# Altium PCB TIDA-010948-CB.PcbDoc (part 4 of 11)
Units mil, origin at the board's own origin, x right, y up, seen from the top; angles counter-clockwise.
Board outline 8100 x 8400 mil, 8 copper layers (L01 - TOP, L02 - GND, L03 - SIG, L04 - GND, L05 - PWR, L06 - SIG, L07 - GND, L08 - BOTTOM), stack 59.656 mil thick; 711 components, 572 nets, 2646 pads, 1325 vias.
Unrouted connection lines stored in the file: 988.
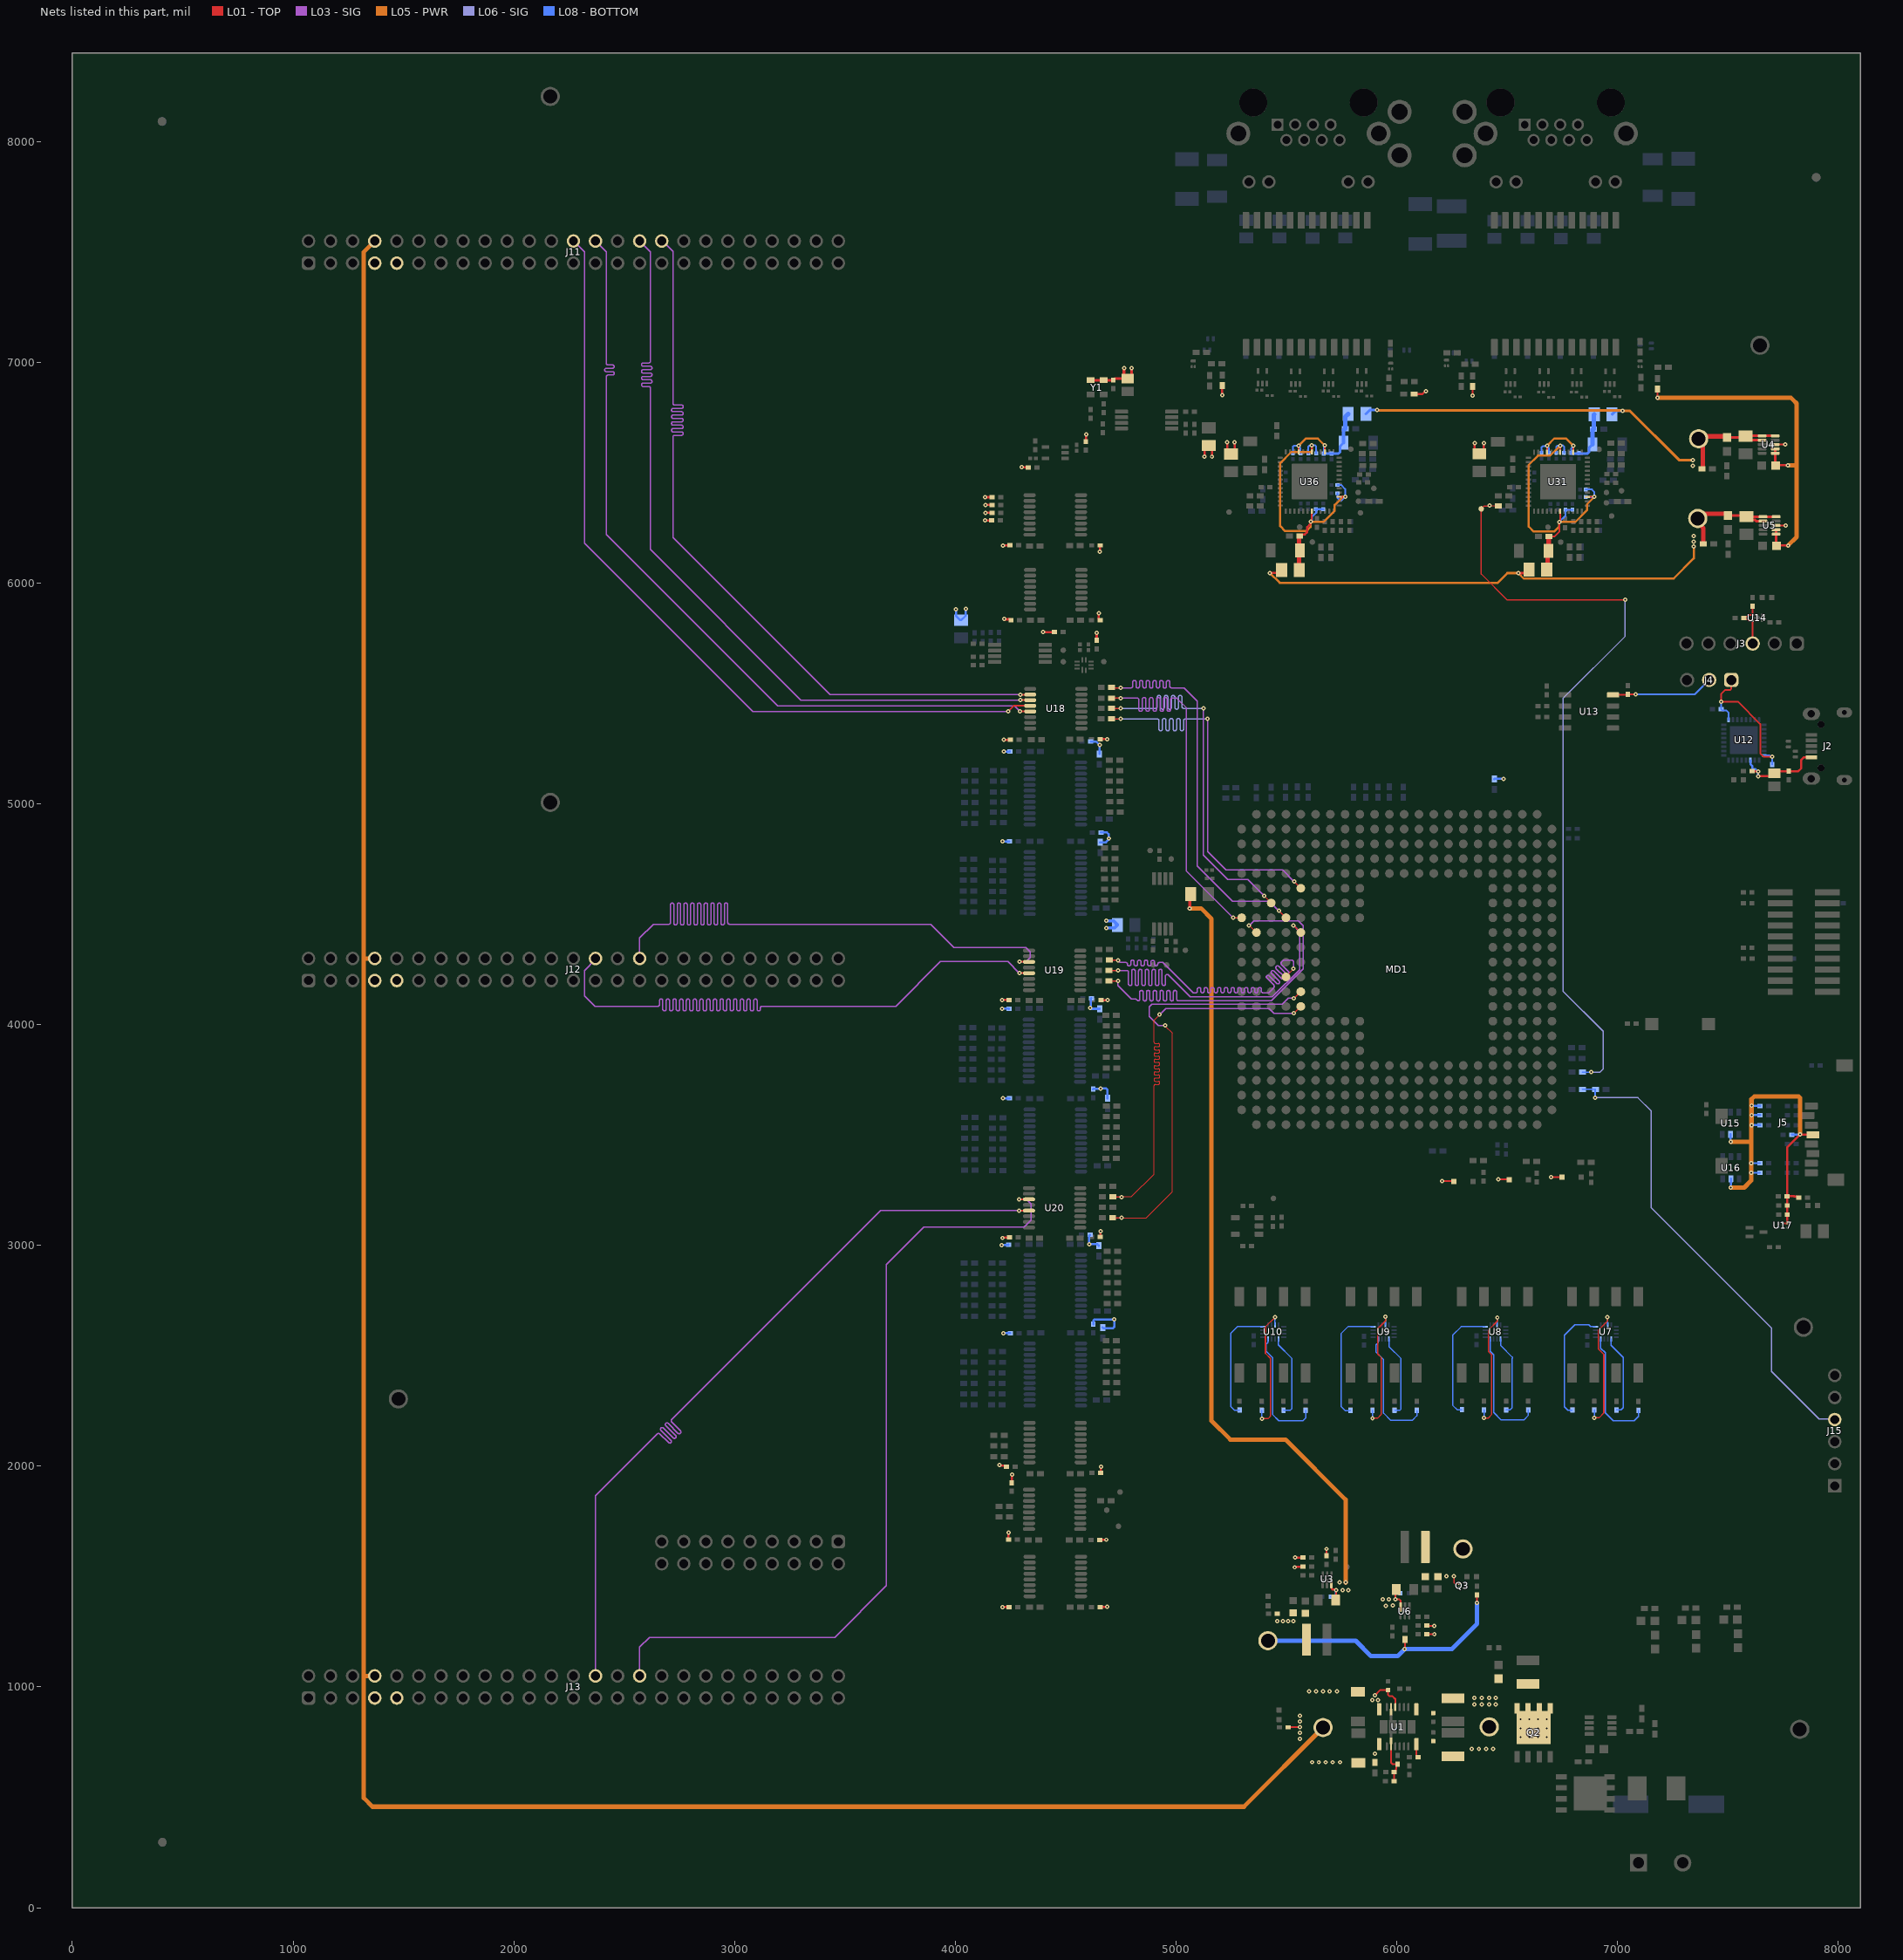
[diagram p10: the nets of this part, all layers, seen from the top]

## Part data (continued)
R229 R231 R245 R248 R269 R271 R285 R287: library part CMP-0021425-3, "RES, 75.0, 1%, 0.125 W, AEC-Q200 Grade 0, 0805", Manufacturer=Vishay-Dale, Power_W=125mW, Supplier Part Number 1=541-75.0CCT-ND, TempCo="100 ppm/C", Tolerance_%=1%, Value2=0.125W, Value_Code=75R0, ValueDisplayed=75.0
R235 R275: library part CMP-0025975-3, "RES, 11.0 k, 1%, 0.063 W, AEC-Q200 Grade 0, 0402", Manufacturer=Vishay-Dale, Power_W=63mW, Supplier Part Number 1=541-11.0KLCT-ND, TempCo="100 ppm/C", Tolerance_%=1%, Value2=0.063W, Value_Code=11k0, ValueDisplayed=11.0k
R236: library part CMP-0026890-5, "RES, 2.2 k, 5%, 0.063 W, AEC-Q200 Grade 0, 0402", Manufacturer=Vishay-Dale, Power_W=63mW, Supplier Part Number 1=541-2.2KJCT-ND, TempCo="200 ppm/C", Tolerance_%=5%, Value2=0.063W, Value_Code=2k20, ValueDisplayed=2.2k
R240 R244 R250 R251 R280 R284 R289 R290: library part CMP-0026852-1, "RES, 1.0 k, 5%, 0.063 W, 0402", Manufacturer=Vishay-Dale, Power_W=63mW, Supplier Part Number 1=541-1.0KJCT-ND, TempCo="200 ppm/C", Tolerance_%=5%, Value2=0.063W, Value_Code=1k00, ValueDisplayed=1.0k
R242 R243 R282 R283: library part CMP-0026231-2, "RES, 2.20 k, 1%, 0.063 W, AEC-Q200 Grade 0, 0402", Manufacturer=Vishay-Dale, Power_W=63mW, Supplier Part Number 1=541-2.20KLCT-ND, TempCo="100 ppm/C", Tolerance_%=1%, Value2=0.063W, Value_Code=2k20, ValueDisplayed=2.20k
R249 R252 R288: library part CMP-0016081-3, "RES, 1.0 M, 5%, 0.75 W, AEC-Q200 Grade 0, 2010", Manufacturer=Vishay-Dale, Power_W=750mW, Supplier Part Number 1=541-1.0MWCT-ND, TempCo="200 ppm/C", Tolerance_%=5%, Value2=0.75W, Value_Code=1M00, ValueDisplayed=1.0M
R311 R312 R313: library part CMP-0025332-3, "RES, 49.9 k, 0.5%, 0.1 W, 0603", Manufacturer="Yageo America", Power_W=100mW, TempCo="50 ppm/C", Tolerance_%=0.5%, Value2=0.1W, Value_Code=49k9, ValueDisplayed=49.9k
R314 R315 R316: library part CMP-0025223-3, "RES, 3.40 k, 0.5%, 0.1 W, 0603", Manufacturer="Yageo America", Power_W=100mW, TempCo="50 ppm/C", Tolerance_%=0.5%, Value2=0.1W, Value_Code=3k40, ValueDisplayed=3.40k
S1: library part CMP-0002196-2, "Switch, Tactile, SPST, 12 V, SMD", CurrentRating_mA=50A, Manufacturer="Wurth Elektronik", Supplier Part Number 1=31T8978
SW1 SW2 SW3 SW4: library part CMP-0096367-1, "Dip Switch SPST 4 Position Surface Mount Slide (Standard) Actuator 25mA 24VDC", Coil Resistance_ohm=50mΩ, Contact Current Rating=25mA, Digikey Part Number=732-6963-1-ND, Manufacturer="Wurth Electronics", Mouser Part Number=710-418121270804, Operating Temperature Range="-40°C to +85°C"
T1 T2: library part CMP-0086582-1, "WURTH ELEKTRONIK LAN TRANSFORMER, 10/100/1000 BASE-T", Manufacturer="Wurth Electronics"
TP1 TP2 TP3 TP4 TP5 TP6 TP7 TP8 TP9 TP34 TP40 TP41: library part CMP-0055160-1, "Test Point, Multipurpose, Purple, TH", Color=Purple, Manufacturer=Keystone, Supplier Part Number 1=36-5129-ND
TP10 TP11 TP12 TP13 TP14 TP15 TP16 TP17 TP18 TP19 TP20 TP21 TP22 TP23 TP24 TP25 TP26 TP27 TP28 TP29 TP30 TP31 TP32 TP33 TP35 TP36 TP37 TP38 TP39: library part CMP-0078143-3, "TEST POINT.  No entry in BOM.", Manufacturer=N/A
U1: library part CMP-0093355-3, "Cruzline-6A Power Module 36Vin 1 Ajustable-Output 1-6V B3QFN20 200-2200kHz SW Freq", Manufacturer="Texas Instruments", Max Supply Voltage=36V, Min Supply Voltage=3V, Operating Temperature Range="-40°C to +125°C", Output Voltage=1-6V, Switching Frequency=200-2200kHz
U2: library part CMP-0095578-1, "Low IQ High Side Switch Controller With Reverse Polarity and Overvoltage Protection", Manufacturer="Texas Instruments", Max Supply Voltage=60V, Min Supply Voltage=4V, Nominal Supply Current=45uA, Operating Temperature Range="-40°C to +150°C"
U3 U6: library part CMP-0083727-1, "4-A Step-Down Converter with 1% Output Accuracy, DMQ0006A (VSON-HR-6)", Alternate Manufacturer="Texas Instruments", Alternate PartNumber=TPS62827DMQR
U4 U5: library part CMP-0860376-1, "1A and 2-A High Efficiency Step-Down Converter MicroSiPTM with Integrated Inductor, SIL0010D (uSIP-10)", Alternate Manufacturer="Texas Instruments", Alternate PartNumber=TPSM82822SILT
U7 U8 U9 U10: library part CMP-0086167-2, "Low-capacitance, 2:1 (SPDT) 4-channel, powered-off protection switch with 1.8 V logic, RSV0016A (UQFN-16)", Alternate Manufacturer="Texas Instruments", Operating Temperature Range="-40 to 125 C", Rating=Catalog
U11: library part CMP-0051315-2, "Single Bus Buffer Gate with 3-State Output, DBV0005A (SOT-23-5)", F @ Nom Voltage(Max)(Mhz)=75, Generic Part Number=SN74AHC1G125, ICC @ Nom Voltage(Max)(mA)=0.01, Manufacturer="Texas Instruments", Operating Temperature Range="-40 to 125 C", Rating=Catalog, tpd @ Nom Voltage(Max)(ns)=11.5,7.5, Voltage(Nom)(V)=3.3,5
U12: library part CMP-0004929-1, "Future Technology Devices International Ltd. FT232R USB UART IC, QFN32", Manufacturer=FTDI, Supplier Part Number 1=768-1008-1-ND
U13: library part CMP-0085670-1, "High Speed, Robust EMC Reinforced Dual-Channel Digital Isolator, D0008B (SOIC-8)", Alternate Manufacturer="Texas Instruments", Alternate PartNumber=ISO7021DR, Operating Temperature Range="-55 to 125 C", PartNumber=ISO7021D, Rating=Catalog
U14: library part CMP-0035981-2, "Single Output Low Noise LDO, 200 mA, Fixed 3.3 V Output, 2 to 5.5 V Input, 4-pin X2SON(DQN), -40 to 85 degC, Green (RoHS & no Sb/Br)", Alternate Manufacturer="Texas Instruments", Alternate PartNumber=TLV70733DQNR
U15 U16: library part CMP-0043117-1, "ESD Solution for High-Speed Differential Interface, 4 Channels, -40 to +85 degC, 6-pin SOT-32 (DBV), Green (RoHS & no Sb/Br)", Breakdown Voltage(Min)(V)=9, Differential Capacitance(pF)=0.05, IO Capacitance(Typ)(pF)=0.8, IO Leakage Current(nA)=10, Manufacturer="Texas Instruments"
U17: library part CMP-0066658-1, "5.5V, 3A, 13.8mΩ Load Switch with Reverse Current Protection, YZP0006AFAF (DSBGA-6)", Alternate Manufacturer="Texas Instruments", Alternate PartNumber=TPS22963CYZPT
U18 U19 U20 U41 U42 U43 U44 U45: library part CMP-0079319-1, "Quad-Bit Bus Transceiver with Configurable Voltage Translation and 3-State Outputs, PW0016A (TSSOP-16)", Alternate Manufacturer="Texas Instruments", Alternate PartNumber=SN74AXC4T245PWR
U21: library part CMP-0860382-1, "SN74AXC2T245RSW, RSW0010A (UQFN-10)", Alternate Manufacturer="Texas Instruments"
U22: library part CMP-0091149-1, "Clock Clock Buffer IC 1:4 250MHz 8-TSSOP (0.173\", 4.40mm Width)", Digikey Part Number=296-LMK1C1102PWRCT-ND, Manufacturer="Texas Instruments", Max Supply Voltage=3.465V, Min Supply Voltage=1.71V, Mouser Part Number=595-LMK1C1102PWR, Nominal Supply Current=25-33000uA, Operating Temperature Range="-40°C to +125°C"
U23 U24: library part CMP-0096980-1, "1.8-V, 2.5-V, and 3.3-V LVCMOS Clock Buffer Family", Digikey Part Number=296-LMK1C1104PWRCT-ND, Manufacturer="Texas Instruments", Max Supply Voltage=3.465V, Min Supply Voltage=1.71V, Mouser Part Number=595-LMK1C1104PWR, Nominal Supply Current=25-33000uA, Operating Temperature Range="-40°C to +125°C"
U25 U26 U27 U28 U29 U30: library part CMP-0065205-4, "Asynchronous Communication Between Data Buses, PW0024A (TSSOP-24)", Alternate Manufacturer="Texas Instruments", Alternate PartNumber=SN74AXC8T245PWT, Operating Temperature Range="-40 to 125 C", Rating=Catalog
U31 U36: library part CMP-0091377-1, "1/1 Transceiver Ethernet 48-VQFN (7x7)", Digikey Part Number=296-53377-1-ND, Manufacturer="Texas Instruments", Max Supply Voltage=3.45V, Min Supply Voltage=990mV, Mouser Part Number=595-DP83869HMRGZT, Operating Temperature Range="-40°C to +125°C"
U32 U33 U34 U35 U37 U38 U39 U40: library part CMP-0066602-2, "Dual-Channel High-Speed ESD Protection, DRL0005A (SOT-OTHER-5)", Alternate Manufacturer="Texas Instruments"
U46: library part CMP-0078475-5, "1-Bit Dual-Supply Buffered Voltage Signal Converter, DCK0005A (SOT-SC70-5)", Manufacturer="Texas Instruments"
Y1: library part CMP-0096024-1, "High-Performance BAW Oscillator", Frequency Stability=25ppm, Frequency_Fixed=25MHz, Load Capacitance=30pF, Manufacturer="Texas Instruments", Max Supply Current=50mA, Max Supply Voltage=3.465V, Min Supply Voltage=2.375V, Operating Temperature Range="-40°C to +105°C"

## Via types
v1: diameter 19.68, hole 7.87, L01 - TOP to L08 - BOTTOM, 1310 vias
v2: diameter 20, hole 7.87, L01 - TOP to L08 - BOTTOM, tented both sides, 7 vias
v3: diameter 200, hole 144, L01 - TOP to L08 - BOTTOM, 6 vias
v4: diameter 20, hole 8, L01 - TOP to L08 - BOTTOM, tented both sides, 2 vias

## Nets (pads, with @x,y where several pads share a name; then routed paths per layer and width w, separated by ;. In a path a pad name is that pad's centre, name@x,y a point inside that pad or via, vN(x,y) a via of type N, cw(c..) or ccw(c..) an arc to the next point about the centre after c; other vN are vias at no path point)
1V1: C23.1 C24.1 L8.2 L11.2 R20.2 TP7.1 U5.5 U5.6 U5.7 | length 2745.9
  L01 - TOP w10: v1(5425.5,6045.5) 5464.5,6045.5 L11.2@5478,6059 ; v1(6550.36,6045.03) 6583.53,6045.03 L8.2@6599,6060.5
  L01 - TOP w12: C23.1@7499.61,6305.54 7580.11,6305.54 C24.1@7584.61,6301.05 C24.1@7585.24,6300.42 ; U5.7@7659.08,6280.73 7627.92,6280.73 7622.63,6286.03 7599.63,6286.03 C24.1@7585.24,6300.42 ; U5.5@7718.14,6300.42 U5.6@7659.08,6300.42 C24.1@7585.24,6300.42
  L01 - TOP w20: R20.2@7388.99,6178.05 7388.99,6248.88 7363.5,6274.37 TP7.1@7363.5,6292.5 7384.05,6313.05 7492.1,6313.05 C23.1@7499.61,6305.54
  L05 - PWR w10: v1(5425.5,6045.5) 5469.46,6001.54 6457.4,6001.54 6500.89,6045.03 v1(6550.36,6045.03) 6574.89,6020.5 7254,6020.5 7345.61,6112.11 v1(7345.61,6165.05)
  other v1: 7345.61,6188.05 7345.61,6212.05
1V1_ETH1: C116.1 C117.1 C118.1 C119.1 C123.1 C129.1 C130.1 C131.1 L8.1 U31.6 U31.31 U31.39 | length 1522.8
  L01 - TOP w8: C123.1@6689.62,6211.5 6715.21,6211.5 6735.86,6232.15 v1(6735.86,6277.03) 6735.86,6280.19 6739.84,6284.17 U31.31@6739.84,6325.14 ; U31.6@6739.85,6592.87 v1(6739.85,6622.52) ; U31.39@6863.86,6390.1 6863.97,6389.99 6895.1,6389.99 v1(6895.21,6389.88)
  L01 - TOP w20: L8.1@6679,6060.5 6682.71,6064.21 6682.71,6142.29 C116.1@6686.43,6146 6688.03,6147.6 6688.03,6209.9 C123.1@6689.62,6211.5
  L05 - PWR w10: v1(6739.85,6622.52) 6694.08,6576.75 6639.55,6576.75 6597.13,6534.33 6597.13,6255.87 6619.85,6233.15 6712.52,6233.15 6735.86,6256.49 v1(6735.86,6277.03) 6808.53,6277.03 6861.5,6330 6861.5,6356.17 v1(6895.21,6389.88)
  L08 - BOTTOM w8: C118.1@6722.5,6589.99 6722.5,6617.31 6727.19,6622 6739.33,6622 v1(6739.85,6622.52) 6740.33,6623 6752.81,6623 6757.5,6618.31 C130.1@6757.5,6589.99 ; v1(6735.86,6277.03) 6764,6305.17 C117.1@6764,6332.01 C129.1@6796,6332.01 ; C119.1@6855.99,6389.5 6856.26,6389.76 6895.09,6389.76 6895.36,6390.03 6895.36,6412.14 6884,6423.5 C131.1@6855.99,6423.5
1V1_ETH2: C158.1 C159.1 C160.1 C161.1 C165.1 C171.1 C172.1 C173.1 L11.1 U36.6 U36.31 U36.39 | length 1559.8
  L01 - TOP w8: v1@5614.98,6284.65 U36.31@5614.98,6325.61 ; U36.6@5614.98,6593.33 v1(5615,6623) ; U36.39@5739,6390.57 5739.21,6390.79 5765.79,6390.79 v1(5766,6391)
  L01 - TOP w10: C165.1@5560.12,6213.5 5566.93,6220.31 5583.31,6220.31 5594,6231 5594,6253 5604,6263 5605.14,6263 5609.15,6267 5609.15,6275.65 v1(5611,6277.5)
  L01 - TOP w20: L11.1@5558,6059 5558,6211.69 5559.81,6213.5 C165.1@5560.12,6213.5
  L05 - PWR w10: v1(5615,6623) 5614.99,6599.19 5609.13,6593.33 5521.51,6593.33 5471.51,6543.33 5471.51,6258.1 5494.45,6235.15 5590.65,6235.15 5609.5,6254 5609.5,6276 v1(5611,6277.5) 5668.94,6277.5 5718.79,6327.35 5718.79,6353.68 5756.11,6391 v1(5766,6391)
  L08 - BOTTOM w8: C173.1@5599.5,6586.99 5599.5,6617.31 5604.19,6622 5614,6622 v1(5615,6623) 5630.31,6623 5635,6618.31 C161.1@5635,6586.99 ; C160.1@5730.99,6407 5730.99,6386.06 5742.71,6374.34 5749.34,6374.34 v1(5766,6391) 5766,6426.03 5747.53,6444.5 C172.1@5730.99,6444.5
  L08 - BOTTOM w10: v1@5615.34,6284.46 5615.34,6299.4 5634.67,6318.72 5634.67,6332.34 C159.1@5633,6334.01 C171.1@5666.5,6334.01
1V8: C25.1 C26.1 C27.1 D20.1 D21.1 D22.1 L2.2 L3.2 L5.2 L6.2 L9.2 Q3.1 R24.2 R129.1 R130.1 R157.1 R158.1 R185.1 R199.1 R236.2 R241.2 R276.2 R291.2 R319.2 R320.2 R322.2 R324.2 R326.2 R328.2 R330.2 R332.2 R334.2 R336.2 R339.2 R341.2 R343.2 TP8.1 U4.3 U5.3 | length 1875.6
  L01 - TOP w6: v1(6259,1501) 6259,1472 6264.27,1466.73 Q3.1@6284.2,1466.73
  L01 - TOP w8: R24.2@6135.69,1277.5 6136.19,1277 6169.5,1277 v1(6170,1276.5) ; C25.1@6136.19,1238.5 v1(6170.5,1238.5) ; v1(6204.5,3291.5) 6205.5,3290.5 6258.19,3290.5 D20.1@6259.19,3289.5 ; v1(6459,3299) 6459.5,3298.5 6509.69,3298.5 D21.1@6510.19,3298 ; v1(6698,3310) 6698.75,3309.25 6747.94,3309.25 D22.1@6748.69,3308.5 ; U4.3@7714.12,6627.26 7714.26,6627.13 7758.87,6627.13 v1(7759,6627) ; U5.3@7718.14,6261.05 7718.41,6260.77 7760.73,6260.77 v1(7761,6260.5)
  L01 - TOP w10: R343.2@4591,6640.69 4591.75,6641.44 4591.75,6672.25 v1(4592.5,6673) ; R319.2@4640,5740.69 4640.5,5741.19 4640.5,5774.5 v1(4641,5775) ; v1(4650,5863.5) 4650,5835.84 4654.84,5831 R339.2@4656.69,5831 ; R332.2@4654.69,1665.5 4655.19,1666 4684,1666 v1(4684.5,1666.5) ; v1(4655,6142) 4656.09,6143.09 4656.09,6169.41 R334.2@4657.19,6170.5 ; R241.2@4655.69,5293 4655.94,5292.75 4686.75,5292.75 v1(4687,5292.5) ; R336.2@4656.19,1361.5 4656.69,1362 4688,1362 v1(4688.5,1362.5) ; R291.2@4656.19,3037.5 4657.34,3038.66 4657.34,3063.84 v1(4658.5,3065) ; R341.2@4658.69,1970.5 4659.09,1970.91 4659.09,1997.59 v1(4659.5,1998) ; R276.2@4659.69,4110.5 4660.19,4111 4689.5,4111 v1(4690,4111.5) ; v1(5129,6573) 5129,6604 L3.2@5148,6623 5163,6608 v1(5163,6572.5) ; v1(5231.5,6637.5) 5231.5,6602 L9.2@5249,6584.5 5265,6600.5 v1(5265,6637.5) ; v1@6354,6632 v1(6353,6633) 6353,6605.5 6373,6585.5 L6.2@6374,6585.5 ; L6.2@6374,6584 6394,6604 6394,6633 v1(6394.5,6633.5)
  L08 - BOTTOM w10: R328.2@4610.35,3047.9 4610.03,3047.9 4605.19,3043.06 4605.19,3007.31 v1(4607,3005.5) 4643.19,3005.5 4650,2998.69 R185.1@4650,2998.12 ; v1@4611.25,4075.25 v1(4611.5,4075.5) 4613.35,4077.35 4613.35,4116.94 R320.2@4616.33,4119.92 ; R322.2@4613.13,5282.03 4637.47,5282.03 v1(4653.5,5266) 4653.25,5265.75 4653.25,5226.37 R129.1@4653,5226.12 ; v1@4618,4071.62 R130.1@4653.5,4071.62 ; R324.2@4624.5,3707.69 4625.91,3709.09 4656.59,3709.09 v1(4658,3710.5) 4683.5,3710.5 4689.68,3704.32 R158.1@4689.68,3665.82 ; R330.2@4625.19,2643.06 4625.19,2658.64 4631.05,2664.5 v1(4720,2664.5) 4720,2631.22 4712.78,2624 4672.12,2624 R199.1@4667.98,2628.14 ; R157.1@4655.5,4825.62 4682.31,4825.62 4694.65,4837.96 4694.65,4841.15 v1(4696.5,4843) 4694.65,4844.85 4694.65,4862.85 4687,4870.5 R326.2@4660.19,4870.5 ; R236.2@6442,5112.12 6442.88,5113 v1(6484.5,5113)
  L08 - BOTTOM w15: v1(4683.5,4438) 4721.5,4438 L5.2@4734,4450.5 4734,4452.5 4716.5,4470 v1(4683.5,4470)
  other v1: 6224,1501
2V5: C16.1 C19.1 L7.2 L10.2 R15.2 TP6.1 U4.5 U4.6 U4.7 | length 2263.2
  L01 - TOP w12: C16.1@7496.6,6658.76 7574.09,6658.76 C19.1@7580.6,6665.26 ; U4.7@7655.07,6646.95 7598.91,6646.95 C19.1@7580.6,6665.26 ; U4.5@7714.12,6666.63 U4.6@7655.07,6666.63 7581.97,6666.63 C19.1@7580.6,6665.26
  L01 - TOP w20: TP6.1@7367.5,6679.14 TP6.1@7367.5,6653.5 ; TP6.1@7374.89,6662.86 TP6.1@7379.62,6652.42 ; R15.2@7382.98,6517.26 7383.79,6517.26 7385.6,6519.08 7385.6,6635.4 TP6.1@7367.5,6653.5 ; C16.1@7494.09,6661.26 C16.1@7496.6,6658.76 7490.86,6664.5 7378.5,6664.5 TP6.1@7367.5,6653.5
  L05 - PWR w12: v1@5910.5,6782.5 v1(5911,6783) 5912.2,6781.8 7022.08,6781.8 v1(7023.29,6780.59) 7054.91,6780.59 7278.24,6557.26 v1(7341.6,6557.26)
  L08 - BOTTOM w12: L10.2@5860,6766 5877,6783 v1(5911,6783) ; L7.2@6974.79,6763.59 6991.79,6780.59 v1(7023.29,6780.59)
  other v1: 7341.6,6531.26
2V5_ETH1: C113.1 C114.1 C115.1 C122.1 C127.1 C128.1 L7.1 U31.3 U31.9 | length 595.3
  L01 - TOP w8: U31.9@6680.79,6592.86 U31.9@6680.79,6592.86 v1(6680.82,6621.99) ; U31.3@6798.9,6592.86 v1(6798.88,6622.51)
  L05 - PWR w10: v1(6680.82,6621.99) 6713.83,6655 6766.39,6655 v1(6798.88,6622.51)
  L08 - BOTTOM w8: C128.1@6655.3,6589.75 6655.3,6613.86 6662.2,6620.75 6679.58,6620.75 v1(6680.82,6621.99) 6680.82,6618.83 6688.99,6610.67 6688.99,6590.24 C115.1@6689.61,6589.61 ; C114.1@6790,6589.51 6790,6610.56 6798.88,6619.44 v1(6798.88,6622.51)
  L08 - BOTTOM w12: C114.1@6790,6589.51 6792.26,6587.25 6864.28,6587.25 6871.31,6594.28 6871.31,6612.7 C113.1@6886.96,6628.35
  L08 - BOTTOM w20: C113.1@6886.96,6628.35 6886.96,6694.28 6888.77,6696.09 C122.1@6891.17,6696.09 6892.98,6697.9 6892.98,6761.78 L7.1@6894.79,6763.59
2V5_ETH2: C155.1 C156.1 C157.1 C164.1 C169.1 C170.1 L10.1 U36.3 U36.9 | length 606.4
  L01 - TOP w8: v1(5556,6622.5) v1(5556,6622.5) U36.9@5555.96,6593.37 ; U36.3@5674.02,6593.35 v1(5674,6623) ; U36.9@5555.93,6593.33 U36.9@5555.96,6593.37
  L05 - PWR w10: v1(5556,6622.5) 5587.5,6654 5643,6654 v1(5674,6623)
  L08 - BOTTOM w8: C157.1@5529,6586.99 5529,6617.81 5533.69,6622.5 v1(5556,6622.5) 5556,6619.34 5564,6611.34 C170.1@5564,6586.99 ; C169.1@5669,6586.49 5669,6614.84 5674,6619.84 v1(5674,6623)
  L08 - BOTTOM w12: C169.1@5669,6586.49 C156.1@5704,6586.49 5735.49,6586.49 5743.37,6594.37 5743.37,6619.95 C155.1@5759.02,6635.6
  L08 - BOTTOM w15: C155.1@5759.02,6635.6 5759.02,6694.69 5763.33,6699 C164.1@5766.88,6699
  L08 - BOTTOM w20: C164.1@5766.88,6699 5766.88,6752.88 L10.1@5780,6766
3V3: C14.1 C15.1 C17.1 C18.1 C22.1 C57.1 C58.1 J11.7 J11.9 J12.7 J12.9 J13.7 J13.9 L1.2 L4.2 R13.2 R14.2 R16.2 R21.2 R22.2 R240.2 R244.1 R268.2 R280.2 R281.2 R284.1 R292.1 R296.1 R297.1 R298.1 R299.1 R317.2 R318.2 R321.2 R323.2 R325.2 R327.2 R329.2 R331.2 R333.2 R335.2 R337.2 R338.2 R340.2 R342.2 TP5.1 U4.1 U4.2 U5.1 U5.2 Y1.1 Y1.4 | length 4191.2
  L01 - TOP w8: R13.2@5682,1593.69 v1(5682,1625) ; v1(6036,1172) 6036.5,1172.5 6036.5,1213.88 R22.2@6037,1214.38 ; R284.1@6078.5,6856 6116.34,6856 6129.34,6869 v1(6132.5,6869) v1@6127,6869 ; v1(6342.5,6849) 6342.75,6849.25 6342.75,6889.63 R240.2@6343,6889.88 ; v1(6363,1381) R21.2@6363,1417.16 ; v1(7181,6840) 7181.25,6840.25 7181.25,6879.13 R244.1@7181.5,6879.38
  L01 - TOP w10: v1(4135.27,6283.27) 4135.37,6283.36 4164.87,6283.36 R296.1@4164.96,6283.46 ; v1(4135.27,6388.51) 4135.52,6388.76 4166.07,6388.76 R299.1@4166.31,6389 ; v1(4136,6353.5) 4136.25,6353.75 4166.06,6353.75 R298.1@4166.31,6354 ; v1(4137,6318) R297.1@4163.15,6318 ; v1(4200.5,2005.5) 4203.12,2005.5 4205.78,2002.84 4225.97,2002.84 R342.2@4230.81,1998 ; v1(4211.5,4112) 4212,4111.5 4242.81,4111.5 R281.2@4243.31,4111 ; v1(4214,1362) 4214.5,1361.5 4243.31,1361.5 R337.2@4243.81,1361 ; v1(4214,3033.5) 4215.75,3035.25 4243.06,3035.25 R317.2@4244.81,3037 ; v1(4215.5,6170) 4216.5,6171 4245.81,6171 R335.2@4246.81,6172 ; v1(4219,5290.5) 4219.5,5290 4249.81,5290 R268.2@4250.31,5289.5 ; v1(4221.5,5837.5) 4223.35,5835.65 4248.96,5835.65 R340.2@4252.31,5832.3 ; R333.2@4240.81,1667 4240.91,1667.09 4240.91,1698.41 v1(4241,1698.5) ; R292.1@4255.5,1925.18 4256,1925.68 4256,1961.5 v1(4256.5,1962) ; v1(4301,6525) 4301.46,6524.54 4330.5,6524.54 R338.2@4330.96,6524.08 ; v1(4397.5,5778) 4397.75,5777.75 4448.56,5777.75 R318.2@4448.81,5777.5 ; R280.2@5209,6893.88 5209.25,6893.63 5209.25,6851.75 v1(5209.5,6851.5) ; v1(5538,1542) 5539.75,1543.75 5573.56,1543.75 R16.2@5575.31,1545.5 ; v1(5539,1586) C14.1@5575.31,1586 ; C15.1@7714.12,6534.23 7714.86,6533.5 v1(7772.5,6533.5) ; C22.1@7720.1,6169.05 7721.1,6170.05 v1(7772.61,6170.05)
  L01 - TOP w12: Y1.1@4612.97,6918.98 Y1.4@4672.03,6918.98 C57.1@4715.5,6918.98 ; C57.1@4719.34,6924.93 4715.5,6921.08 C57.1@4715.5,6919.19 4723.22,6926.9 C58.1@4780.05,6926.9 ; v1(4764.05,6974.37) 4764.05,6942.56 4779.7,6926.9 C58.1@4780.05,6926.9 ; v1(4798.55,6973.87) 4798.55,6942.56 4782.9,6926.9 C58.1@4780.05,6926.9 ; U4.2@7714.12,6607.58 U4.1@7714.12,6587.89 7714.12,6534.23 C15.1@7716.09,6532.26 ; U5.2@7718.14,6241.36 U5.1@7718.14,6221.68 7718.14,6171.02 C22.1@7720.1,6169.05
  L05 - PWR w20: v1(7181,6840) 7784.5,6840 7795.97,6828.53 7811,6813.5 7811,6532.86 ; v1(7772.5,6533.5) 7810.36,6533.5 7811,6532.86 ; v1(7772.61,6170.05) 7811,6208.44 7811,6532.86
  L08 - BOTTOM w10: v1(4003,5882) 4003,5852 4023,5832 L4.2@4026,5832 4027,5832 4047,5852 v1(4047,5882.5) ; v1(4210,3001.5) 4210.75,3002.25 4240.06,3002.25 R329.2@4240.81,3003 ; v1(4212.5,4072) 4212.75,4071.75 4242.56,4071.75 R321.2@4242.81,4071.5 ; v1(4214,4830) R327.2@4245.31,4830 ; v1(4216,3666) R325.2@4246.31,3666 ; v1(4217.5,2602) 4217.75,2602.25 4248.56,2602.25 R331.2@4248.81,2602.5 ; v1(4219,5236.5) 4219.5,5237 4246.31,5237 R323.2@4246.81,5237.5
  L08 - BOTTOM w20: TP5.1@5416,1209 5814,1209 5883.5,1139.5 6003.5,1139.5 v1(6036,1172) 6249.5,1172 6363,1285.5 v1(6363,1381)
  other v1: 5508,1298 5532,1298 5459,1299 5484,1299
3V3_SD: C44.1 C45.1 J5.4 R68.2 R69.2 R70.2 R71.2 R72.2 R89.2 R90.2 R91.2 U15.5 U16.5 U17.A1 U17.B1 | length 1829.7
  L01 - TOP w8: U17.B1@7749,3099.84 U17.A1@7768.69,3099.84 C44.1@7768.68,3140
  L01 - TOP w10: R89.2@7768.19,3181.5 R90.2@7768.19,3222.5 ; C44.1@7768.68,3140 R89.2@7768.69,3181 ; R91.2@7821.31,3217 7817.76,3220.56 7802.01,3220.56 7800.07,3222.5 R90.2@7768.19,3222.5 ; J5.4@7885.3,3501.61 7885.11,3501.81 7827.19,3501.81 v1(7827,3502) 7768.19,3443.19 R90.2@7768.19,3222.5
  L05 - PWR w20: v1(7512,3469) 7605.61,3469 7605.93,3468.68 ; v1(7513,3262) 7574,3262 7605,3293 v1(7605,3328) 7605.93,3328.93 7605.93,3468.68 ; v1(7827,3502) 7827,3667.5 7820.5,3674 7618.71,3674 7606.71,3662 v1(7606.71,3633.9) v1(7606.71,3589.7) 7606.71,3544.29 v1(7606.85,3544.15) 7605.93,3543.22 7605.93,3468.68
  L08 - BOTTOM w8: v1(7605,3328) R72.2@7645.31,3328 ; v1(7606,3372) R71.2@7645.31,3372
  L08 - BOTTOM w10: v1(7512,3469) U15.5@7512,3502.8 ; v1(7513,3262) U16.5@7513,3301.8 ; v1(7606.71,3589.7) 7606.86,3589.85 7645.16,3589.85 R69.2@7645.31,3590 ; v1(7606.71,3633.9) 7607.66,3632.95 7644.36,3632.95 R68.2@7645.31,3632 ; v1(7606.85,3544.15) 7607.28,3544.57 7644.89,3544.57 R70.2@7645.31,3545 ; C45.1@7789.68,3501 7790.18,3501.5 7826.5,3501.5 v1(7827,3502)
3V3_USB_EX: C39.1 J3.3 R67.2 U14.3 U14.4 | length 233
  L01 - TOP w8: J3.3@7612,5726 U14.4@7612,5830.41 7594.59,5830.41 7588.84,5836.16 7578.53,5836.16 C39.1@7572.68,5842 7578.53,5847.84 7587.84,5847.84 7596,5856 U14.3@7612,5856 R67.2@7612,5895.31
3V3_USB_FTDI: C36.1 J4.1 R62.1 U12.1 U12.16 | length 725.8
  L01 - TOP w8: J4.1@7515,5561 7515,5521 7510,5516 7488,5516 7469,5497 v1(7469,5463) 7545,5463 7647,5361 7647,5229 7663,5213 v1(7700,5213)
  L08 - BOTTOM w8: v1(7469,5463) 7468.84,5462.84 7468.84,5429.16 C36.1@7468.69,5429 7474.53,5423.16 7491.84,5423.16 7503.57,5411.43 U12.1@7503.57,5380.38 U12.1@7505,5381.81 ; U12.16@7664,5219.94 7687.81,5219.94 7692.52,5215.24 7697.76,5215.24 v1(7700,5213) 7700.5,5212.5 7700.5,5178.19 R62.1@7701,5177.69
3V3_USB_ISO: C34.1 J4.2 U13.8 | length 464.2
  L01 - TOP w8: U13.8@6979.27,5493 6980.93,5494.66 7045.34,5494.66 C34.1@7047,5496.31 7047.16,5496.16 7081.84,5496.16 v1(7082,5496)
  L08 - BOTTOM w8: v1(7082,5496) 7350,5496 J4.2@7415,5561
5V: C6.1 C7.1 C8.2 C12.2 C13.1 C20.2 C21.1 J11.8 J12.8 J13.8 L12.2 R3.2 R7.2 TP9.1 U1.5 U1.8 U1.9 U3.6@5703.69,1468.28 U6.6@6017.31,1361.72 | length 15783.2
  L01 - TOP w8: R7.2@5507.37,817 5507.87,817.5 5561.5,817.5 v1(5562,818) ; U3.6@5703.69,1468.28 5705.59,1466.38 5705.59,1443.69 5708.04,1441.24 5722.76,1441.24 v1(5725,1439) 5725,1394.63 C13.1@5723.37,1393 ; v1(5901,962) 5924.31,985.32 C8.2@5961,985.32 5961,963.32 5966.84,957.47 5980.53,957.47 5993.63,944.37 U1.5@5993.63,908 ; C21.1@5997.63,1441 5994,1437.37 v1(5994,1397) 6011,1397 6017.31,1390.68 U6.6@6017.31,1361.72
  L01 - TOP w15: v1(5062,4526.5) 5062,4586 L12.2@5066.5,4590.5
  L05 - PWR w20: J13.8@1370,1050 1321.15,1050 1320.5,1050.65 ; J12.8@1370,4299.6 1320.81,4299.6 1320.5,4299.29 ; J11.8@1370,7549.2 1320.5,7499.7 1320.5,4299.29 ; v1(5062,4526.5) 5113.18,4526.5 5160.5,4479.18 5160.5,2205.51 5245.51,2120.5 5496.13,2120.5 5768,1848.63 v1(5768,1473) ; TP9.1@5666,816 5307.5,457.5 1359.5,457.5 1320.5,496.5 1320.5,1050.65 ; 1320.5,1050.65 1320.5,4299.29
  L08 - BOTTOM w8: C12.2@5701.69,1409 5707.53,1414.84 5720.31,1414.84 5722.76,1417.29 5722.76,1436.76 v1(5725,1439) ; v1(5994,1397) 5994,1420 5999,1425 C20.2@6016.31,1425
  other v1: 5616,659 5647,659 5678,659 5709,659 5742,659 5900,698 5562,764 5562,792 5562,844 5562,870 5889,941 5915,941 5603,980 5634,980 5665,980 5696,980 5729,980 5950,1368 5981,1369 5936,1396 5965,1397 5754,1439 5781,1439 5740,1473
5V_USB: C37.1 C38.1 J2.1 R64.2 U12.19 | length 420.4
  L01 - TOP w10: R64.2@7609.69,5149 7610.69,5148 7636,5148 v1(7637,5147) ; v1(7637,5125) 7697.47,5125 C38.1@7710,5137.53 7720.16,5147.69 C37.1@7776,5147.69 7818.68,5147.69 7832,5161 7832,5199 7842.82,5209.82 J2.1@7878,5209.82
  L08 - BOTTOM w10: U12.19@7601.99,5197.31 7602.9,5196.4 7602.9,5178.1 7611,5170 7611,5161 7614,5158 7623.38,5158 7634.38,5147 v1(7637,5147) v1(7637,5125)
24V: C1.2 C2.2 C4.2 C5.2 C10.2 Q2.5 Q2.6 Q2.7 Q2.8 Q2.9 R1.2 R2.1 TP34.1 U1.1 U1.16 | length 61.8
  L01 - TOP w8: U1.16@6089.1,740.68 6089.1,687.84 6094.94,682 R2.1@6095.69,682
  other v1: 6339,719 6372,719 6405,719 6436,719 6560,773 6600,773 6640,773 6680,773 6560,813 6600,813 6640,813 6680,813 6560,853 6600,853 6640,853 6680,853 6352,921 6385,921 6418,921 6449,921 6352,950 6385,950 6418,950 6449,950
AGND: C9.2 NT1.1 NT2.1 R6.1 R8.1 U1.6 U1.11 | length 237.6
  L01 - TOP w8: U1.6@5973.94,908 5974,907.94 NT2.1@5974,886 ; NT1.1@5974,755 5973.94,754.94 U1.11@5973.94,730.83 ; U1.11@5974.87,729.91 U1.11@5973.94,730.83 ; R6.1@5988.19,573 C9.2@5988.19,614.5 ; C9.2@5988.69,615 5990.16,615 5996,620.84 5996,628 5998.16,630.16 5998.16,643.47 R8.1@6004,649.32 6002.31,651 5980,651 5973.94,657.06 U1.11@5973.94,730.83
Bootmode0: R27.1 U7.16 | length 527.2
  L08 - BOTTOM w5: R27.1@6795,2253.32 6775.69,2253.32 6760,2269 6760,2592 6807.5,2639.5 6869.5,2639.5 6877.38,2631.62 U7.16@6899.76,2631.62
Bootmode1: R29.1 U7.3 | length 584.2
  L01 - TOP w6: v1(6895,2219) 6916,2219 6938,2241 6938,2506 6914,2530 6914,2617 6954.44,2657.44 6954.44,2674.56 v1(6954,2675)
  L08 - BOTTOM w6: v1(6895,2219) R29.1@6895,2254.32 ; v1(6954,2675) 6954.44,2674.56 6954.44,2639.93 U7.3@6954.87,2639.5
Bootmode2: R31.1 U7.9 | length 369.9
  L08 - BOTTOM w5: U7.9@6970.62,2576.5 6970.62,2547.38 7026,2492 7026,2265 7015.31,2254.32 R31.1@6995,2254.32
Bootmode3: R33.1 U7.12 | length 545
  L08 - BOTTOM w5: U7.12@6923.38,2576.5 6923.38,2533.62 6944,2513 6944,2242 6981,2205 7075,2205 7095,2225 R33.1@7095,2252.32
Bootmode4: R43.1 U8.16 | length 530.3
  L08 - BOTTOM w6: R43.1@6295,2255.32 6273.69,2255.32 6253,2276 6253,2593 6291.62,2631.62 U8.16@6399.76,2631.62
Bootmode5: R45.1 U8.3 | length 572.5
  L01 - TOP w6: v1(6395,2218) 6414,2218 6430,2234 6430,2504 6416,2518 6416,2617.31 6455,2656.31 v1(6455,2673)
  L08 - BOTTOM w6: v1(6395,2218) R45.1@6395,2254.32 ; U8.3@6454.87,2639.5 6454.94,2639.56 6454.94,2672.94 v1(6455,2673)
Bootmode6: R47.1 U8.9 | length 366.1
  L08 - BOTTOM w6: U8.9@6470.62,2576.5 6470.62,2546.38 6523.51,2493.49 6523.51,2488.51 6523,2488 6523,2265 6512.31,2254.32 R47.1@6495,2254.32
Bootmode7: R49.1 U8.12 | length 543.2
  L08 - BOTTOM w6: U8.12@6423.38,2576.5 6423.38,2519.62 6439,2504 6439,2243 6472,2210 6576,2210 6596,2230 R49.1@6596,2254.32
Bootmode8: R28.1 U9.16 | length 540.7
  L08 - BOTTOM w6: R28.1@5790,2252.32 5788.69,2251 5767,2251 5747,2271 5747,2600 5778.62,2631.62 U9.16@5893.76,2631.62
Bootmode9: R30.1 U9.3 | length 581.2
  L01 - TOP w6: v1(5890,2217) 5913,2217 5929,2233 5929,2493 5914,2508 5914,2622.81 5949,2657.81 v1(5949,2676)
  L08 - BOTTOM w6: v1(5890,2217) R30.1@5890,2252.32 ; U9.3@5948.87,2639.5 5948.94,2639.56 5948.94,2675.94 v1(5949,2676)
Bootmode10: R32.1 U9.9 | length 372.4
  L08 - BOTTOM w6: U9.9@5964.62,2576.5 5964.62,2541.38 6019,2487 6019,2258 6013.31,2252.32 R32.1@5990,2252.32
Bootmode11: R34.1 U9.12 | length 551.6
  L08 - BOTTOM w6: U9.12@5917.38,2576.5 5916.44,2575.57 5916.44,2560.35 5905.5,2549.41 5905.5,2516.42 5940,2481.92 5940,2240 5972,2208 6071,2208 6091,2228 R34.1@6091,2251.32
Bootmode12: R44.1 U10.16 | length 535.9
  L08 - BOTTOM w6: R44.1@5288,2253.32 5264.69,2253.32 5248,2270 5248,2602 5277.62,2631.62 U10.16@5392.76,2631.62
Bootmode13: R46.1 U10.3 | length 590.8
  L01 - TOP w6: v1(5389,2215) 5417,2215 5428,2226 5428,2488 5405,2511 5405,2631 v1(5448,2674)
  L08 - BOTTOM w6: v1(5389,2215) R46.1@5389,2252.32 ; U10.3@5447.87,2639.5 5447.94,2639.56 5447.94,2673.94 v1(5448,2674)
Bootmode14: R48.1 U10.9 | length 381.7
  L08 - BOTTOM w6: U10.9@5463.62,2576.5 5463.62,2549.38 5524,2489 5524,2260 5516.31,2252.32 R48.1@5487,2252.32
Bootmode15: R50.1 U10.12 | length 559.5
  L08 - BOTTOM w6: U10.12@5416.38,2576.5 5415.5,2575.63 5415.5,2559 5407.3,2550.8 5407.3,2521.7 5437,2492 5437,2234 5465,2206 5575,2206 5587,2218 R50.1@5587,2252.32
CLKOUT0: R304.1 R305.1 TP21.1 | length 3496.3
  L01 - TOP w4.25: v1(6420.36,6351.03) 6458.35,6351.03 R305.1@6459.88,6349.5
  L01 - TOP w6: v1(6420.36,6351.03) 6417.74,6348.41 6394.91,6348.41 TP21.1@6382.5,6336 6382.5,6041 6499.5,5924 v1(7034,5924)
  L06 - SIG w6: v1(6880,3784.5) 6920,3784.5 6935,3799.5 6935,3969.59 6752.81,4151.78 6752.81,5476.81 7034.5,5758.5 7034.5,5923.5 v1(7034,5924)
  L08 - BOTTOM w6: R304.1@6841.12,3785 6841.62,3784.5 v1(6880,3784.5)
DAC_DIAG: C135.1 J15.4 R308.1 | length 2158.9
  L06 - SIG w6: v1(6898.5,3669) 7092.5,3669 7152.5,3609 7152.5,3171.06 7697.5,2626.06 7697.5,2429 7912.5,2214 7981,2214 J15.4@7984,2211
  L08 - BOTTOM w6: R308.1@6840.62,3707 6899.38,3707 C135.1@6899.88,3706.5 6898.5,3705.12 v1(6898.5,3669)
DOUT_A1: MD1.F5 R95.1 | length 1913.6
  L01 - TOP w6: R95.1@4708,5385.19 4708.4,5384.79 v1(4749.46,5384.79) ; v1(5534.5,4647.99) 5534.59,4647.99 5564.87,4617.71 MD1.F5@5564.96,4617.71
  L03 - SIG w5.25: v1(5143,5385) 5143,4783 5225.6,4700.4 5482.1,4700.4 v1(5534.5,4647.99)
  L06 - SIG w6: v1(4749.46,5384.79) 4895.33,5384.79 4914.33,5384.79 cw(c4914.33,5376.79) 4922.33,5376.79 4922.33,5338.9 ccw(c4930.33,5338.9) 4938.33,5338.9 4938.33,5378.42 cw(c4946.33,5378.42) 4954.33,5378.42 4954.33,5338.9 ccw(c4962.33,5338.9) 4970.33,5338.9 4970.33,5378.42 cw(c4978.33,5378.42) 4986.33,5378.42 4986.33,5338.9 ccw(c4994.33,5338.9) 5002.33,5338.9 5002.33,5378.42 cw(c5010.33,5378.42) 5018.33,5378.42 5018.33,5338.9 ccw(c5026.33,5338.9) 5034.33,5338.9 5034.33,5376.79 cw(c5042.33,5376.79) 5042.33,5384.79 5077,5384.79 v1@5143,5384.79
DOUT_A1_SDM: J11.28 U18.13 | length 3734.3
  L01 - TOP w8: v1(4293.3,5418.18) U18.13@4339.15,5418.19
  L03 - SIG w5.25: J11.28@2370,7549.2 2419,7500.2 2419,6998.12 2419,6995.5 ccw(c2426.62,6995.5) 2426.62,6987.87 2447.16,6987.87 cw(c2447.16,6980.25) 2447.16,6972.62 2418.98,6972.62 ccw(c2418.98,6965) 2418.98,6957.37 2447.16,6957.37 cw(c2447.16,6949.75) 2447.16,6942.12 2426.62,6942.12 ccw(c2426.62,6934.5) 2419,6934.5 2419,6916.96 2419,6219.5 3194.5,5444 4267.48,5444 v1(4293.3,5418.18)
DOUT_A2: MD1.H1 R97.1 | length 1988.2
  L01 - TOP w6: R97.1@4708.5,5478.69 4708.59,5478.79 v1(4748.96,5478.79) ; v1(5258,4484) 5258.07,4483.93 MD1.H1@5297.24,4483.85 MD1.H1@5297.24,4483.85
  L03 - SIG w6: v1(4748.96,5478.79) 4804.42,5478.79 4823.42,5478.79 cw(c4823.42,5470.79) 4831.42,5470.79 4831.42,5426.89 ccw(c4839.42,5426.89) 4847.42,5426.89 4847.42,5473.76 cw(c4855.42,5473.76) 4863.42,5473.76 4863.42,5426.89 ccw(c4871.42,5426.89) 4879.42,5426.89 4879.42,5473.76 cw(c4887.42,5473.76) 4895.42,5473.76 4895.42,5426.89 ccw(c4903.42,5426.89) 4911.42,5426.89 4911.42,5473.76 cw(c4919.42,5473.76) 4927.42,5473.76 4927.42,5426.89 ccw(c4935.42,5426.89) 4943.42,5426.89 4943.42,5473.76 cw(c4951.42,5473.76) 4959.42,5473.76 4959.42,5426.89 ccw(c4967.42,5426.89) 4975.42,5426.89 4975.42,5470.79 cw(c4983.42,5470.79) 4983.42,5478.79 5002.71,5478.79 5010.25,5471.25 5047,5434.5 5047,4695 v1(5258,4484)
DOUT_A2_SDM: J11.32 U18.11 | length 3734.3
  L01 - TOP w8: v1(4294.3,5469.68) 4294.45,5469.53 U18.11@4339.01,5469.53
  L03 - SIG w5.25: J11.32@2570,7549.2 2618.5,7500.7 2618.5,7022.39 2618.5,7004.51 cw(c2610.88,7004.51) 2610.88,6996.89 2586.01,6996.89 ccw(c2586.01,6989.26) 2586.01,6981.64 2618.42,6981.64 cw(c2618.42,6974.01) 2618.42,6966.39 2586.01,6966.39 ccw(c2586.01,6958.76) 2586.01,6951.14 2618.42,6951.14 cw(c2618.42,6943.51) 2618.42,6935.89 2586.01,6935.89 ccw(c2586.01,6928.26) 2586.01,6920.64 2618.42,6920.64 cw(c2618.42,6913.01) 2618.42,6905.39 2586.01,6905.39 ccw(c2586.01,6897.76) 2586.01,6890.14 2610.88,6890.14 cw(c2610.88,6882.51) 2618.5,6882.51 2618.5,6847.94 2618.5,6152 3300.82,5469.68 v1(4294.3,5469.68)
DOUT_A3: MD1.J2 R99.1 | length 1988.2
  L01 - TOP w6: R99.1@4695.91,4197.5 v1(4737,4197.5) ; v1(5330.5,4448.5) 5331.55,4448.5 5363.13,4416.92 MD1.J2@5364.17,4416.92
  L03 - SIG w5.25: v1(4737,4197.5) 4737,4178 4798.16,4116.84 4817.66,4116.84 4826.83,4107.67 4827.91,4107.67 ccw(c4827.91,4115.3) 4835.53,4115.3 4835.53,4147.07 cw(c4843.16,4147.07) 4850.78,4147.07 4850.78,4114.62 ccw(c4858.41,4114.62) 4866.03,4114.62 4866.03,4147.07 cw(c4873.66,4147.07) 4881.28,4147.07 4881.28,4114.62 ccw(c4888.91,4114.62) 4896.53,4114.62 4896.53,4147.07 cw(c4904.16,4147.07) 4911.78,4147.07 4911.78,4114.62 ccw(c4919.41,4114.62) 4927.03,4114.62 4927.03,4147.07 cw(c4934.66,4147.07) 4942.28,4147.07 4942.28,4114.62 ccw(c4949.91,4114.62) 4957.53,4114.62 4957.53,4147.07 cw(c4965.16,4147.07) 4972.78,4147.07 4972.78,4114.62 ccw(c4980.41,4114.62) 4988.03,4114.62 4988.03,4147.07 cw(c4995.66,4147.07) 5003.28,4147.07 5003.28,4115.3 ccw(c5010.91,4115.3) 5010.91,4107.67 5040.29,4107.67 5432.47,4107.67 5576.89,4252.09 5576.89,4446.97 5554.08,4469.78 5351.78,4469.78 v1(5330.5,4448.5)
DOUT_A3_SDM: J12.28 U19.13 | length 3734.3
  L01 - TOP w8: v1(4290.69,4233.01) U19.13@4336.54,4233.02
  L03 - SIG w5.25: J12.28@2370,4299.6 2370,4295.5 2319.5,4245 2319.5,4130.5 2367,4083 2641.41,4083 2651.96,4083 ccw(c2651.96,4090.62) 2659.59,4090.62 2659.59,4108.2 cw(c2667.21,4108.2) 2674.84,4108.2 2674.84,4069.94 ccw(c2682.46,4069.94) 2690.09,4069.94 2690.09,4108.2 cw(c2697.71,4108.2) 2705.34,4108.2 2705.34,4069.94 ccw(c2712.96,4069.94) 2720.59,4069.94 2720.59,4108.2 cw(c2728.21,4108.2) 2735.84,4108.2 2735.84,4069.94 ccw(c2743.46,4069.94) 2751.09,4069.94 2751.09,4108.2 cw(c2758.71,4108.2) 2766.34,4108.2 2766.34,4069.94 ccw(c2773.96,4069.94) 2781.59,4069.94 2781.59,4108.2 cw(c2789.21,4108.2) 2796.84,4108.2 2796.84,4069.94 ccw(c2804.46,4069.94) 2812.09,4069.94 2812.09,4108.2 cw(c2819.71,4108.2) 2827.34,4108.2 2827.34,4069.94 ccw(c2834.96,4069.94) 2842.59,4069.94 2842.59,4108.2 cw(c2850.21,4108.2) 2857.84,4108.2 2857.84,4069.94 ccw(c2865.46,4069.94) 2873.09,4069.94 2873.09,4108.2 cw(c2880.71,4108.2) 2888.34,4108.2 2888.34,4069.94 ccw(c2895.96,4069.94) 2903.59,4069.94 2903.59,4108.2 cw(c2911.21,4108.2) 2918.84,4108.2 2918.84,4069.94 ccw(c2926.46,4069.94) 2934.09,4069.94 2934.09,4108.2 cw(c2941.71,4108.2) 2949.34,4108.2 2949.34,4069.94 ccw(c2956.96,4069.94) 2964.59,4069.94 2964.59,4108.2 cw(c2972.21,4108.2) 2979.84,4108.2 2979.84,4069.94 ccw(c2987.46,4069.94) 2995.09,4069.94 2995.09,4108.2 cw(c3002.71,4108.2) 3010.34,4108.2 3010.34,4069.94 ccw(c3017.96,4069.94) 3025.59,4069.94 3025.59,4108.2 cw(c3033.21,4108.2) 3040.84,4108.2 3040.84,4069.94 ccw(c3048.46,4069.94) 3056.09,4069.94 3056.09,4108.2 cw(c3063.71,4108.2) 3071.34,4108.2 3071.34,4069.94 ccw(c3078.96,4069.94) 3086.59,4069.94 3086.59,4108.2 cw(c3094.21,4108.2) 3101.84,4108.2 3101.84,4069.94 ccw(c3109.46,4069.94) 3117.09,4069.94 3117.09,4075.38 cw(c3124.71,4075.38) 3124.71,4083 3127.34,4083 3730.2,4083 3932.2,4285 4238.7,4285 v1(4290.69,4233.01)
DOUT_A4: MD1.M4 R101.1 | length 1989.3
  L01 - TOP w6: R101.1@4696.14,4291.5 v1(4736.5,4291.5) ; MD1.M4@5498.03,4216.14 5498.03,4217.83 5532,4251.8 v1(5532,4253.5)
  L03 - SIG w5.25: v1(4736.5,4291.5) 4746.68,4281.32 4754.25,4281.32 4772.13,4281.32 cw(c4772.13,4273.69) 4779.75,4273.69 4779.75,4273.4 ccw(c4787.38,4273.4) 4795,4273.4 4795,4284.45 cw(c4802.63,4284.45) 4810.25,4284.45 4810.25,4273.4 ccw(c4817.88,4273.4) 4825.5,4273.4 4825.5,4284.45 cw(c4833.13,4284.45) 4840.75,4284.45 4840.75,4273.4 ccw(c4848.38,4273.4) 4856,4273.4 4856,4284.45 cw(c4863.63,4284.45) 4871.25,4284.45 4871.25,4273.4 ccw(c4878.88,4273.4) 4886.5,4273.4 4886.5,4283.41 cw(c4894.13,4283.41) 4901.75,4283.41 4901.75,4273.4 ccw(c4909.38,4273.4) 4917,4273.4 4917,4273.69 cw(c4924.63,4273.69) 4924.63,4281.32 4937.4,4281.32 4940.4,4281.32 5077.72,4144 5086.31,4144 5088.94,4144 ccw(c5088.94,4151.62) 5096.56,4151.62 5096.56,4160.54 cw(c5104.19,4160.54) 5111.81,4160.54 5111.81,4151.47 ccw(c5119.44,4151.47) 5127.06,4151.47 5127.06,4160.54 cw(c5134.69,4160.54) 5142.31,4160.54 5142.31,4151.47 ccw(c5149.94,4151.47) 5157.56,4151.47 5157.56,4160.54 cw(c5165.19,4160.54) 5172.81,4160.54 5172.81,4151.47 ccw(c5180.44,4151.47) 5188.06,4151.47 5188.06,4160.54 cw(c5195.69,4160.54) 5203.31,4160.54 5203.31,4151.47 ccw(c5210.94,4151.47) 5218.56,4151.47 5218.56,4160.54 cw(c5226.19,4160.54) 5233.81,4160.54 5233.81,4151.47 ccw(c5241.44,4151.47) 5249.06,4151.47 5249.06,4160.54 cw(c5256.69,4160.54) 5264.31,4160.54 5264.31,4151.47 ccw(c5271.94,4151.47) 5279.56,4151.47 5279.56,4160.54 cw(c5287.19,4160.54) 5294.81,4160.54 5294.81,4151.47 ccw(c5302.44,4151.47) 5310.06,4151.47 5310.06,4160.54 cw(c5317.69,4160.54) 5325.31,4160.54 5325.31,4151.47 ccw(c5332.94,4151.47) 5340.56,4151.47 5340.56,4160.54 cw(c5348.19,4160.54) 5355.81,4160.54 5355.81,4151.47 ccw(c5363.44,4151.47) 5371.06,4151.47 5371.06,4160.54 cw(c5378.69,4160.54) 5386.31,4160.54 5386.31,4151.62 ccw(c5393.94,4151.62) 5393.94,4144 5410.27,4144 5419,4144 5440.81,4165.81 5442.67,4167.67 ccw(c5437.28,4173.06) 5442.67,4178.45 5411.07,4210.05 cw(c5416.46,4215.44) 5411.07,4220.83 cw(c5416.46,4215.44) 5421.86,4220.83 5455.81,4186.88 ccw(c5461.2,4192.28) 5466.59,4186.88 ccw(c5461.2,4192.28) 5466.59,4197.67 5432.64,4231.62 cw(c5438.03,4237.01) 5432.64,4242.4 cw(c5438.03,4237.01) 5443.42,4242.4 5477.37,4208.45 ccw(c5482.76,4213.84) 5488.16,4208.45 ccw(c5482.76,4213.84) 5488.16,4219.23 5454.21,4253.18 cw(c5459.6,4258.58) 5454.21,4263.97 cw(c5459.6,4258.58) 5464.99,4263.97 5498.94,4230.02 ccw(c5504.33,4235.41) 5509.72,4230.02 ccw(c5504.33,4235.41) 5509.72,4240.8 5477.63,4272.89 cw(c5483.02,4278.29) 5477.63,4283.68 5486.5,4292.55 5525.95,4292.55 5532,4286.5 v1(5532,4253.5)
DOUT_A4_SDM: J12.32 U19.11 | length 3736.2
  L01 - TOP w8: v1(4291.69,4284.51) 4291.84,4284.36 U19.11@4336.41,4284.36
  L03 - SIG w5.25: J12.32@2570,4299.6 2570,4392 2632.5,4454.5 2699.42,4454.5 2702.05,4454.5 ccw(c2702.05,4462.12) 2709.68,4462.12 2709.68,4543.12 cw(c2717.3,4543.12) 2724.93,4543.12 2724.93,4458.61 ccw(c2732.55,4458.61) 2740.18,4458.61 2740.18,4543.12 cw(c2747.8,4543.12) 2755.43,4543.12 2755.43,4458.61 ccw(c2763.05,4458.61) 2770.68,4458.61 2770.68,4543.12 cw(c2778.3,4543.12) 2785.93,4543.12 2785.93,4458.61 ccw(c2793.55,4458.61) 2801.18,4458.61 2801.18,4543.12 cw(c2808.8,4543.12) 2816.43,4543.12 2816.43,4458.61 ccw(c2824.05,4458.61) 2831.68,4458.61 2831.68,4543.12 cw(c2839.3,4543.12) 2846.93,4543.12 2846.93,4458.61 ccw(c2854.55,4458.61) 2862.18,4458.61 2862.18,4543.12 cw(c2869.8,4543.12) 2877.43,4543.12 2877.43,4458.61 ccw(c2885.05,4458.61) 2892.68,4458.61 2892.68,4543.12 cw(c2900.3,4543.12) 2907.93,4543.12 2907.93,4458.61 ccw(c2915.55,4458.61) 2923.18,4458.61 2923.18,4543.12 cw(c2930.8,4543.12) 2938.43,4543.12 2938.43,4458.61 ccw(c2946.05,4458.61) 2953.68,4458.61 2953.68,4543.12 cw(c2961.3,4543.12) 2968.93,4543.12 2968.93,4462.12 ccw(c2976.55,4462.12) 2976.55,4454.5 2996.64,4454.5 3889,4454.5 3994.5,4349 4320.5,4349 4339.26,4330.24 4339.26,4304.65 4319.11,4284.51 v1(4291.69,4284.51)
DOUT_A5: MD1.N5 R103.1 | length 1932.5
  L01 - TOP w4.25: v1(4753.71,3124.5) 4864,3124.5 4982.36,3242.86 4982.36,3961.63 4950.24,3993.76 v1(4950.24,3996)
  L01 - TOP w6: R103.1@4712.62,3124.5 v1(4753.71,3124.5) ; v1(5533.5,4119.5) 5534.38,4119.5 5564.08,4149.21 MD1.N5@5564.96,4149.21
  L03 - SIG w5.25: v1(4950.24,3996) 4920,3996 4878,4038 4878,4080 4890,4092 5480.94,4092 5508.44,4119.5 v1(5533.5,4119.5)
DOUT_A5_SDM: J13.28 U20.13 | length 3733.2
  L01 - TOP w8: v1(4288.31,3157.49) U20.13@4334.15,3157.5
  L03 - SIG w5.25: J13.28@2370,1050 2370,1866 2637.41,2133.41 2650.05,2146.05 cw(c2655.44,2140.66) 2660.83,2146.05 2700.68,2106.2 ccw(c2706.07,2111.59) 2711.46,2106.2 ccw(c2706.07,2111.59) 2711.46,2116.99 2666.72,2161.73 cw(c2672.11,2167.12) 2666.72,2172.51 cw(c2672.11,2167.12) 2677.5,2172.51 2722.25,2127.77 ccw(c2727.64,2133.16) 2733.03,2127.77 ccw(c2727.64,2133.16) 2733.03,2138.55 2688.28,2183.3 cw(c2693.68,2188.69) 2688.28,2194.08 cw(c2693.68,2188.69) 2699.07,2194.08 2743.81,2149.34 ccw(c2749.2,2154.73) 2754.6,2149.34 ccw(c2749.2,2154.73) 2754.6,2160.12 2714.75,2199.97 cw(c2720.14,2205.36) 2714.75,2210.75 2729.76,2225.76 3661.49,3157.49 v1(4288.31,3157.49)
DOUT_A6: MD1.P5 R105.1 | length 1932.2
  L01 - TOP w4.25: v1(4753.21,3218.5) 4755.21,3220.5 4798,3220.5 4899.5,3322 4899.5,3705.57 4899.5,3721.94 cw(c4906.62,3721.94) 4906.62,3729.07 4919.35,3729.07 ccw(c4919.35,3736.19) 4919.35,3743.32 4906.61,3743.32 cw(c4906.61,3750.44) 4906.61,3757.57 4919.35,3757.57 ccw(c4919.35,3764.69) 4919.35,3771.82 4906.61,3771.82 cw(c4906.61,3778.94) 4906.61,3786.07 4919.35,3786.07 ccw(c4919.35,3793.19) 4919.35,3800.32 4906.61,3800.32 cw(c4906.61,3807.44) 4906.61,3814.57 4919.35,3814.57 ccw(c4919.35,3821.69) 4919.35,3828.82 4906.61,3828.82 cw(c4906.61,3835.94) 4906.61,3843.07 4919.35,3843.07 ccw(c4919.35,3850.19) 4919.35,3857.32 4906.61,3857.32 cw(c4906.61,3864.44) 4906.61,3871.57 4919.35,3871.57 ccw(c4919.35,3878.69) 4919.35,3885.82 4906.61,3885.82 cw(c4906.61,3892.94) 4906.61,3900.07 4919.35,3900.07 ccw(c4919.35,3907.19) 4919.35,3914.32 4906.62,3914.32 cw(c4906.62,3921.44) 4899.5,3921.44 4899.5,3933.41 4899.5,4019 v1(4925.5,4045) v1@4922.88,4047.62
  L01 - TOP w6: R105.1@4712.85,3218.5 v1(4753.21,3218.5) ; v1(5533,4051) 5533.34,4051 5564.62,4082.28 MD1.P5@5564.96,4082.28
  L03 - SIG w5.25: v1(4925.5,4045) 4953.36,4072.86 5422.57,4072.86 5444.42,4051 v1(5533,4051)
DOUT_A6_SDM: J13.32 U20.11 | length 3735.4
  L01 - TOP w8: v1(4289.31,3208.99) 4289.45,3208.84 U20.11@4334.02,3208.84
  L03 - SIG w5.25: J13.32@2570,1050 2570,1180 2614.5,1224.5 3453.5,1224.5 3687.61,1458.61 3687.61,2371.36 3687.61,2434.1 3687.61,2912.61 3858,3083 4311.48,3083 4342.28,3113.8 4342.28,3187.62 4320.91,3208.99 v1(4289.31,3208.99)
DOUT_B1: MD1.G3 R96.1 | length 1915
  L01 - TOP w6: R96.1@4708.5,5432.19 4708.59,5432.29 v1(4749.46,5432.29) ; v1(5399,4583.5) 5399,4583.19 5431.1,4551.09 MD1.G3@5431.1,4550.78
  L03 - SIG w5.25: v1(5124.5,5432) 5124,5431.5 5124,4768.5 5234.75,4657.75 5324.75,4657.75 v1(5399,4583.5)
  L06 - SIG w6: v1(4749.46,5432.29) 4903.7,5432.29 4906.71,5432.29 ccw(c4906.71,5440.29) 4914.71,5440.29 4914.71,5482.98 cw(c4922.71,5482.98) 4930.71,5482.98 4930.71,5436.41 ccw(c4938.71,5436.41) 4946.71,5436.41 4946.71,5482.98 cw(c4954.71,5482.98) 4962.71,5482.98 4962.71,5436.41 ccw(c4970.71,5436.41) 4978.71,5436.41 4978.71,5482.98 cw(c4986.71,5482.98) 4994.71,5482.98 4994.71,5436.41 ccw(c5002.71,5436.41) 5010.71,5436.41 5010.71,5482.98 cw(c5018.71,5482.98) 5026.71,5482.98 5026.71,5440.29 ccw(c5034.71,5440.29) 5034.71,5432.29 5070.5,5432.29 v1@5124.25,5432.29
DOUT_B1_SDM: J11.26 U18.12 | length 3735.3
  L01 - TOP w8: v1(4239,5418) 4264.74,5443.74 U18.12@4339.1,5443.74
  L03 - SIG w5.25: J11.26@2270,7549.2 2320,7499.2 2320,6180 3082,5418 v1(4239,5418)
DOUT_B2: MD1.H4 R98.1 | length 1989.5
  L01 - TOP w5.25: R98.1@4708.5,5526.69 4709.9,5525.29 v1(4748.46,5525.29)
  L01 - TOP w6: v1(5466,4515.5) 5466.19,4515.5 5497.84,4483.85 MD1.H4@5498.03,4483.85
  L03 - SIG w5.25: v1(4748.46,5525.29) 4793.52,5525.29 4796.15,5525.29 ccw(c4796.15,5532.91) 4803.77,5532.91 4803.77,5551.1 cw(c4811.4,5551.1) 4819.02,5551.1 4819.02,5532.12 ccw(c4826.65,5532.12) 4834.27,5532.12 4834.27,5551.1 cw(c4841.9,5551.1) 4849.52,5551.1 4849.52,5532.12 ccw(c4857.15,5532.12) 4864.77,5532.12 4864.77,5551.1 cw(c4872.4,5551.1) 4880.02,5551.1 4880.02,5532.12 ccw(c4887.65,5532.12) 4895.27,5532.12 4895.27,5551.1 cw(c4902.9,5551.1) 4910.52,5551.1 4910.52,5532.12 ccw(c4918.15,5532.12) 4925.77,5532.12 4925.77,5551.1 cw(c4933.4,5551.1) 4941.02,5551.1 4941.02,5532.12 ccw(c4948.65,5532.12) 4956.27,5532.12 4956.27,5551.1 cw(c4963.9,5551.1) 4971.52,5551.1 4971.52,5532.91 ccw(c4979.15,5532.91) 4979.15,5525.29 5003.52,5525.29 5035.86,5525.29 5095,5466.15 5095,4719.5 5256.4,4558.1 5423.4,4558.1 v1(5466,4515.5)
DOUT_B2_SDM: J11.34 U18.10 | length 3734.3
  L01 - TOP w8: v1(4294.3,5494.37) 4294.61,5494.67 U18.10@4338.85,5494.67
  L03 - SIG w5.25: J11.34@2670,7549.2 2673.3,7549.2 2720.5,7502 2720.5,6816.75 2720.5,6814.13 ccw(c2728.12,6814.13) 2728.12,6806.5 2759.93,6806.5 cw(c2759.93,6798.88) 2759.93,6791.25 2721.86,6791.25 ccw(c2721.86,6783.63) 2721.86,6776 2759.93,6776 cw(c2759.93,6768.38) 2759.93,6760.75 2721.86,6760.75 ccw(c2721.86,6753.13) 2721.86,6745.5 2759.93,6745.5 cw(c2759.93,6737.88) 2759.93,6730.25 2721.86,6730.25 ccw(c2721.86,6722.63) 2721.86,6715 2759.93,6715 cw(c2759.93,6707.38) 2759.93,6699.75 2721.86,6699.75 ccw(c2721.86,6692.13) 2721.86,6684.5 2759.93,6684.5 cw(c2759.93,6676.88) 2759.93,6669.25 2728.12,6669.25 ccw(c2728.12,6661.63) 2720.5,6661.63 2720.5,6623 2720.5,6206.5 3432.63,5494.37 v1(4294.3,5494.37)
DOUT_B3: MD1.J5 R100.1 | length 1990.5
  L01 - TOP w6: R100.1@4695.91,4245 v1(4737,4245) ; v1(5531.5,4449) 5532.19,4449 5564.27,4416.92 MD1.J5@5564.96,4416.92
  L03 - SIG w5.25: v1(4737,4245) 4758.84,4245 4776.71,4245 cw(c4776.71,4237.38) 4784.34,4237.38 4784.34,4184.51 ccw(c4791.96,4184.51) 4799.59,4184.51 4799.59,4242.87 cw(c4807.21,4242.87) 4814.84,4242.87 4814.84,4184.51 ccw(c4822.46,4184.51) 4830.09,4184.51 4830.09,4242.87 cw(c4837.71,4242.87) 4845.34,4242.87 4845.34,4184.51 ccw(c4852.96,4184.51) 4860.59,4184.51 4860.59,4242.87 cw(c4868.21,4242.87) 4875.84,4242.87 4875.84,4184.51 ccw(c4883.46,4184.51) 4891.09,4184.51 4891.09,4242.87 cw(c4898.71,4242.87) 4906.34,4242.87 4906.34,4184.51 ccw(c4913.96,4184.51) 4921.59,4184.51 4921.59,4242.87 cw(c4929.21,4242.87) 4936.84,4242.87 4936.84,4184.51 ccw(c4944.46,4184.51) 4952.09,4184.51 4952.09,4219.51 cw(c4959.71,4219.51) 4965.1,4224.9 4983.21,4206.79 5064.5,4125.5 5435.8,4125.5 5559.27,4248.97 5559.27,4421.23 v1(5531.5,4449)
